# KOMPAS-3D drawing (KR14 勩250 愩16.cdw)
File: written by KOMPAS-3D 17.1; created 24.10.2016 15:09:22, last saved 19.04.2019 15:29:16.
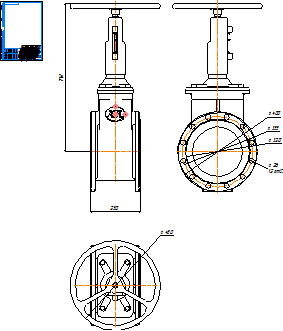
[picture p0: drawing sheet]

Sheet 1: A4, portrait

Title block, sheet 1: name: KR14 Ду250 Ру16; material: Внимание! Данный продукт является объектом авторского права ООО «Торговый Дом АДЛ». / Запрещается изменение, копирование, распространение / (в том числе путем копирования на другие сайты и ресурсы в Интернете) / или любое иное использование информации и объектов без предварительного / согласия правообладателя (ООО «Торговый Дом АДЛ»).; mass: 200,4; sheets: 1; organisation: ООО "Торговый дом АДЛ"; sheet format: A4; stored path: \\adlc.lan\data\АДЛ_ПКД\3D-модели\ADL production\Клиновые задвижки серии KR ГРАНАР\Клиновые задвижки KR14\kompas 2d\KR14 Ду250 Ру16.cdw

Views: Вид 1, Проекционный вид 3
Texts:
  Klimkovich
  ADL
Dimensions and other numbers on the sheet: 250; 742; 450; 1:1; 1; 200,4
